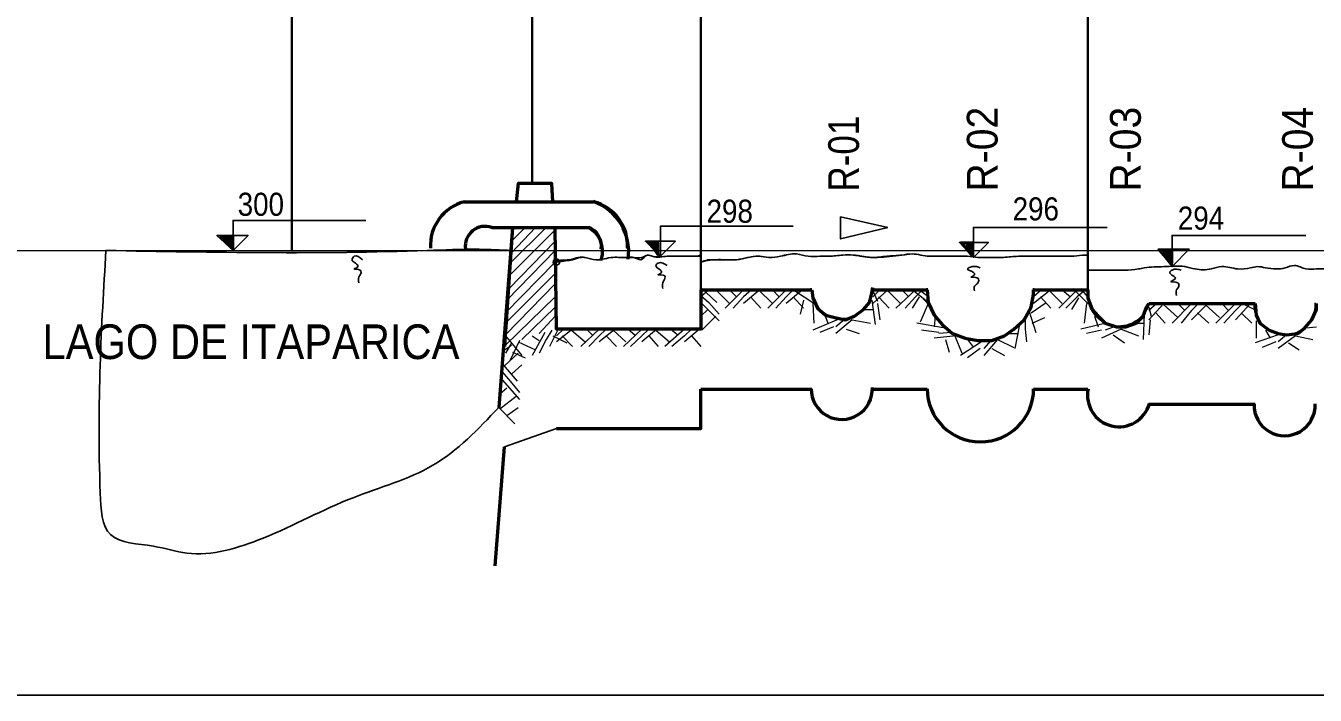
# Model space of a CAD drawing. Extents: x 8426.2 to 8495.4, y 19933.5 to 19963.2.
# Drawn here: x 8432.42 to 8443.58, y 19944.82 to 19950.61 of the extents above; entities that cross this region are included whole.
import ezdxf

# ---------------------------------------------------------------- set-up
doc = ezdxf.new("R2010")
doc.units = 0
doc.header["$LTSCALE"] = 0.11
doc.header["$PDMODE"] = 32
doc.header["$PDSIZE"] = 0.055
for name, color, linetype, lineweight in [('1', 7, 'Continuous', 35), ('2', 7, 'Continuous', 13), ('3', 7, 'Continuous', 25)]:
    doc.layers.add(name, color=color, linetype=linetype, lineweight=lineweight)

msp = doc.modelspace()

# ---------------------------------------------------------------- linework, layer by layer
at = {"layer": '1', "lineweight": 25}
for points in [[(8435.36, 19948.93), (8434.21, 19948.93), (8434.21, 19948.67), (8434.07, 19948.8), (8434.34, 19948.8), (8434.21, 19948.67)], [(8439.06, 19948.88), (8437.91, 19948.88), (8437.91, 19948.62), (8437.78, 19948.75), (8438.04, 19948.75), (8437.91, 19948.62)], [(8441.78, 19948.87), (8440.62, 19948.87), (8440.62, 19948.61), (8440.5, 19948.74), (8440.75, 19948.74), (8440.62, 19948.61)], [(8443.5, 19948.8), (8442.34, 19948.8), (8442.34, 19948.53), (8442.22, 19948.68), (8442.49, 19948.68), (8442.34, 19948.53)]]:
    msp.add_lwpolyline(points, dxfattribs=at)
at = {"layer": '1'}
for points in [[(8434.21, 19948.68), (8434.1, 19948.79), (8434.21, 19948.79)], [(8440.61, 19948.62), (8440.51, 19948.74), (8440.61, 19948.74)]]:
    msp.add_lwpolyline(points, close=True, dxfattribs=at)
for points in [[(8434.21, 19948.68), (8434.11, 19948.79), (8434.19, 19948.79), (8434.19, 19948.7), (8434.13, 19948.77), (8434.18, 19948.77), (8434.19, 19948.73), (8434.16, 19948.76)], [(8434.18, 19948.74), (8434.17, 19948.77), (8434.15, 19948.76), (8434.19, 19948.73)], [(8437.91, 19948.62), (8437.8, 19948.74), (8437.89, 19948.74), (8437.89, 19948.63), (8437.82, 19948.74), (8437.89, 19948.74), (8437.89, 19948.65), (8437.84, 19948.73), (8437.89, 19948.73), (8437.89, 19948.68), (8437.86, 19948.71)], [(8437.89, 19948.69), (8437.88, 19948.71), (8437.85, 19948.71), (8437.89, 19948.68)], [(8440.61, 19948.62), (8440.53, 19948.73), (8440.6, 19948.73), (8440.6, 19948.65), (8440.56, 19948.71), (8440.6, 19948.71), (8440.6, 19948.67), (8440.57, 19948.7)], [(8440.6, 19948.68), (8440.58, 19948.71), (8440.57, 19948.71), (8440.6, 19948.67)], [(8442.34, 19948.54), (8442.23, 19948.67), (8442.34, 19948.67), (8442.34, 19948.56), (8442.26, 19948.65), (8442.33, 19948.65), (8442.33, 19948.57), (8442.27, 19948.64), (8442.33, 19948.64), (8442.33, 19948.59), (8442.31, 19948.63)], [(8442.33, 19948.62), (8442.32, 19948.64), (8442.28, 19948.63), (8442.33, 19948.59)]]:
    msp.add_lwpolyline(points, dxfattribs=at)
at = {"layer": '1', "lineweight": 25}
for points in [[(8435.33, 19948.59), (8435.26, 19948.62), (8435.24, 19948.59), (8435.27, 19948.56), (8435.29, 19948.53), (8435.26, 19948.51), (8435.31, 19948.5), (8435.32, 19948.48), (8435.3, 19948.44), (8435.3, 19948.39)], [(8437.97, 19948.54), (8437.89, 19948.56), (8437.87, 19948.54), (8437.91, 19948.5), (8437.92, 19948.48), (8437.89, 19948.46), (8437.95, 19948.45), (8437.95, 19948.43), (8437.93, 19948.39), (8437.93, 19948.34)], [(8440.68, 19948.52), (8440.61, 19948.53), (8440.57, 19948.51), (8440.62, 19948.48), (8440.63, 19948.46), (8440.6, 19948.44), (8440.66, 19948.43), (8440.66, 19948.39), (8440.63, 19948.36), (8440.63, 19948.32)], [(8440.68, 19948.52), (8440.61, 19948.53), (8440.57, 19948.51), (8440.62, 19948.48), (8440.63, 19948.46), (8440.6, 19948.44), (8440.66, 19948.43), (8440.66, 19948.39), (8440.63, 19948.36), (8440.63, 19948.32)], [(8442.42, 19948.5), (8442.34, 19948.5), (8442.32, 19948.48), (8442.35, 19948.45), (8442.37, 19948.43), (8442.33, 19948.4), (8442.39, 19948.39), (8442.4, 19948.36), (8442.38, 19948.33), (8442.38, 19948.28)]]:
    msp.add_spline(points, degree=3, dxfattribs=at)
at = {"layer": '2', "lineweight": 35}
for p, q in [((8436.8, 19955.32), (8436.8, 19949.25)), ((8438.26, 19955.32), (8438.26, 19948.33)), ((8441.61, 19955.32), (8441.61, 19948.33)), ((8434.72, 19955.24), (8434.72, 19948.67))]:
    msp.add_line(p, q, dxfattribs=at)
at = {"layer": '2', "lineweight": 53}
for p, q in [((8436.21, 19949.09), (8437.33, 19949.09)), ((8436.45, 19948.87), (8437.3, 19948.87)), ((8436.63, 19948.87), (8436.51, 19947.31)), ((8436.63, 19948.87), (8436.56, 19947.84)), ((8438.26, 19948.33), (8439.22, 19948.33)), ((8439.75, 19948.33), (8440.22, 19948.33)), ((8441.14, 19948.33), (8441.61, 19948.33)), ((8442.14, 19948.21), (8443.06, 19948.21)), ((8438.26, 19947.47), (8439.22, 19947.47)), ((8439.75, 19947.47), (8440.22, 19947.47)), ((8441.14, 19947.47), (8441.61, 19947.47)), ((8442.14, 19947.34), (8443.06, 19947.34)), ((8436.48, 19945.94), (8436.56, 19946.97))]:
    msp.add_line(p, q, dxfattribs=at)
at = {"layer": '2', "lineweight": 25}
for p, q in [((8436.6, 19948.45), (8437, 19948.85)), ((8436.61, 19948.56), (8436.92, 19948.87)), ((8436.62, 19948.65), (8436.83, 19948.87)), ((8436.63, 19948.86), (8436.65, 19948.87)), ((8436.63, 19948.76), (8436.74, 19948.87)), ((8436.58, 19948.24), (8437, 19948.67)), ((8436.6, 19948.34), (8437, 19948.75)), ((8436.57, 19948.13), (8437, 19948.57)), ((8436.57, 19948.04), (8437, 19948.47)), ((8436.57, 19947.94), (8437, 19948.38)), ((8436.57, 19947.85), (8437, 19948.27)), ((8436.71, 19947.9), (8437, 19948.18)), ((8436.86, 19947.95), (8437, 19948.1))]:
    msp.add_line(p, q, dxfattribs=at)
at = {"layer": '2'}
for p, q in [((8438.26, 19948.35), (8438.4, 19948.22)), ((8438.33, 19948.33), (8438.26, 19948.27)), ((8438.39, 19948.33), (8438.51, 19948.21)), ((8438.63, 19948.33), (8438.47, 19948.17)), ((8438.51, 19948.33), (8438.57, 19948.27)), ((8438.7, 19948.33), (8438.63, 19948.27)), ((8438.77, 19948.33), (8438.63, 19948.21)), ((8438.76, 19948.33), (8438.88, 19948.21)), ((8439, 19948.33), (8438.84, 19948.17)), ((8438.88, 19948.33), (8438.94, 19948.27)), ((8439.06, 19948.33), (8439, 19948.27)), ((8439.14, 19948.33), (8439, 19948.21)), ((8439.81, 19948.33), (8439.75, 19948.27)), ((8439.88, 19948.33), (8439.75, 19948.21)), ((8439.87, 19948.33), (8439.99, 19948.21)), ((8440.12, 19948.33), (8439.95, 19948.17)), ((8440, 19948.33), (8440.06, 19948.27)), ((8440.24, 19948.21), (8440.09, 19948.33)), ((8440.18, 19948.33), (8440.12, 19948.27)), ((8440.23, 19948.27), (8440.15, 19948.33)), ((8441.21, 19948.33), (8441.14, 19948.27)), ((8441.29, 19948.33), (8441.14, 19948.21)), ((8441.27, 19948.33), (8441.39, 19948.21)), ((8441.52, 19948.33), (8441.36, 19948.17)), ((8441.39, 19948.33), (8441.46, 19948.27)), ((8441.61, 19948.21), (8441.48, 19948.34)), ((8441.61, 19948.21), (8441.48, 19948.34)), ((8441.59, 19948.33), (8441.52, 19948.27)), ((8441.61, 19948.27), (8441.55, 19948.34)), ((8441.61, 19948.27), (8441.55, 19948.34)), ((8438.26, 19948.28), (8438.33, 19948.22)), ((8438.26, 19948.22), (8438.42, 19948.06)), ((8438.33, 19948.22), (8438.42, 19948.12)), ((8438.63, 19948.27), (8438.54, 19948.17)), ((8438.69, 19948.27), (8438.78, 19948.17)), ((8439, 19948.27), (8438.91, 19948.17)), ((8439.06, 19948.27), (8439.15, 19948.17)), ((8439.24, 19948.21), (8439.07, 19948.32)), ((8439.15, 19948.24), (8439.12, 19948.12)), ((8439.74, 19948.24), (8439.77, 19948.03)), ((8439.75, 19948.32), (8439.79, 19948.23)), ((8439.8, 19948.27), (8439.89, 19948.17)), ((8440.12, 19948.27), (8440.03, 19948.17)), ((8440.15, 19948.27), (8440.09, 19948.17)), ((8440.17, 19948.27), (8440.26, 19948.17)), ((8441.12, 19948.13), (8441.25, 19948.22)), ((8441.2, 19948.27), (8441.29, 19948.17)), ((8441.52, 19948.27), (8441.42, 19948.17)), ((8441.53, 19948.26), (8441.47, 19948.16)), ((8441.53, 19948.26), (8441.47, 19948.16)), ((8438.26, 19948.1), (8438.32, 19948.16)), ((8439.23, 19948.21), (8439.24, 19948.04)), ((8439.33, 19948.12), (8439.36, 19948.04)), ((8439.67, 19948.16), (8439.75, 19948.16)), ((8439.79, 19948.21), (8439.81, 19948.07)), ((8440.23, 19948.21), (8440.16, 19948.05)), ((8441.1, 19948.15), (8441.16, 19947.96)), ((8441.6, 19948.21), (8441.58, 19948.04)), ((8441.6, 19948.21), (8441.58, 19948.04)), ((8442.1, 19948.12), (8442.09, 19947.9)), ((8442.21, 19948.21), (8442.14, 19948.15)), ((8442.27, 19948.21), (8442.14, 19948.07)), ((8442.14, 19948.18), (8442.16, 19948.1)), ((8442.2, 19948.13), (8442.28, 19948.04)), ((8442.27, 19948.2), (8442.39, 19948.09)), ((8442.51, 19948.21), (8442.34, 19948.04)), ((8442.39, 19948.21), (8442.45, 19948.15)), ((8442.51, 19948.15), (8442.42, 19948.04)), ((8442.57, 19948.21), (8442.51, 19948.15)), ((8442.65, 19948.21), (8442.51, 19948.07)), ((8442.56, 19948.13), (8442.66, 19948.04)), ((8442.63, 19948.2), (8442.75, 19948.09)), ((8442.89, 19948.21), (8442.72, 19948.04)), ((8442.77, 19948.21), (8442.83, 19948.15)), ((8442.89, 19948.15), (8442.79, 19948.04)), ((8442.95, 19948.21), (8442.89, 19948.15)), ((8443.02, 19948.21), (8442.89, 19948.07)), ((8442.94, 19948.13), (8443.03, 19948.04)), ((8443.07, 19948.15), (8442.97, 19948.2)), ((8438.27, 19947.98), (8438.39, 19948.1)), ((8439.44, 19948.07), (8439.23, 19947.98)), ((8439.41, 19948.01), (8439.29, 19947.96)), ((8439.5, 19948.07), (8439.43, 19948.01)), ((8439.57, 19948.07), (8439.43, 19947.95)), ((8439.57, 19948.07), (8439.73, 19948.04)), ((8440.36, 19948), (8440.13, 19948.04)), ((8440.29, 19948.1), (8440.28, 19948.01)), ((8441.02, 19948.03), (8440.98, 19947.82)), ((8441.07, 19948.09), (8441.07, 19947.99)), ((8441.13, 19948.04), (8441.24, 19948.09)), ((8441.77, 19948.04), (8441.55, 19947.99)), ((8441.77, 19948.04), (8441.55, 19947.99)), ((8441.67, 19948.1), (8441.7, 19948.01)), ((8441.67, 19948.1), (8441.7, 19948.01)), ((8441.84, 19948.01), (8441.76, 19947.98)), ((8441.84, 19948.01), (8441.76, 19947.98)), ((8442.01, 19948.04), (8442.1, 19948.04)), ((8442.15, 19948.07), (8442.14, 19947.94)), ((8443.07, 19948.06), (8443.07, 19947.91)), ((8443.5, 19948), (8443.59, 19948.01)), ((8436.57, 19947.93), (8436.71, 19947.76)), ((8437.07, 19947.99), (8437.01, 19947.93)), ((8437.15, 19947.99), (8437.01, 19947.88)), ((8437.06, 19947.93), (8437.15, 19947.84)), ((8437.14, 19947.98), (8437.26, 19947.88)), ((8437.38, 19947.99), (8437.22, 19947.84)), ((8437.27, 19947.99), (8437.32, 19947.94)), ((8437.38, 19947.93), (8437.29, 19947.84)), ((8437.44, 19947.99), (8437.38, 19947.93)), ((8437.52, 19947.99), (8437.38, 19947.88)), ((8437.44, 19947.93), (8437.53, 19947.84)), ((8437.5, 19947.98), (8437.61, 19947.88)), ((8437.75, 19947.99), (8437.59, 19947.84)), ((8437.63, 19947.99), (8437.69, 19947.94)), ((8437.75, 19947.93), (8437.65, 19947.84)), ((8437.81, 19947.99), (8437.75, 19947.93)), ((8437.88, 19947.99), (8437.75, 19947.88)), ((8437.81, 19947.93), (8437.89, 19947.84)), ((8437.87, 19947.98), (8437.99, 19947.88)), ((8438.12, 19947.99), (8437.95, 19947.84)), ((8438, 19947.99), (8438.06, 19947.94)), ((8438.12, 19947.93), (8438.01, 19947.84)), ((8438.18, 19947.99), (8438.12, 19947.93)), ((8438.25, 19947.99), (8438.12, 19947.88)), ((8438.18, 19947.93), (8438.26, 19947.84)), ((8439.52, 19947.99), (8439.63, 19947.95)), ((8440.32, 19947.96), (8440.17, 19947.98)), ((8440.47, 19947.93), (8440.28, 19947.91)), ((8440.43, 19947.96), (8440.32, 19947.95)), ((8440.38, 19947.9), (8440.41, 19947.79)), ((8440.46, 19947.93), (8440.52, 19947.78)), ((8440.57, 19947.9), (8440.62, 19947.83)), ((8440.83, 19947.9), (8440.71, 19947.76)), ((8440.77, 19947.89), (8440.71, 19947.82)), ((8440.83, 19947.9), (8440.97, 19947.83)), ((8440.92, 19947.95), (8441.01, 19947.95)), ((8441.07, 19947.99), (8441.08, 19947.88)), ((8441.73, 19947.98), (8441.6, 19947.95)), ((8441.73, 19947.98), (8441.6, 19947.95)), ((8441.9, 19947.99), (8441.73, 19947.91)), ((8441.9, 19947.99), (8441.73, 19947.91)), ((8441.83, 19947.94), (8441.93, 19947.87)), ((8441.83, 19947.94), (8441.93, 19947.87)), ((8441.9, 19947.99), (8442.05, 19947.93)), ((8443.26, 19947.94), (8443.06, 19947.87)), ((8443.15, 19947.98), (8443.19, 19947.91)), ((8443.33, 19947.94), (8443.26, 19947.88)), ((8443.41, 19947.93), (8443.26, 19947.82)), ((8443.41, 19947.93), (8443.56, 19947.9)), ((8436.56, 19947.81), (8436.62, 19947.85)), ((8436.56, 19947.67), (8436.68, 19947.78)), ((8440.69, 19947.88), (8440.51, 19947.76)), ((8440.68, 19947.82), (8440.57, 19947.74)), ((8440.78, 19947.82), (8440.89, 19947.76)), ((8443.24, 19947.88), (8443.12, 19947.83)), ((8443.35, 19947.87), (8443.44, 19947.81)), ((8436.55, 19947.68), (8436.67, 19947.54)), ((8436.62, 19947.6), (8436.71, 19947.68)), ((8436.54, 19947.62), (8436.61, 19947.54)), ((8436.54, 19947.55), (8436.69, 19947.38)), ((8436.52, 19947.43), (8436.58, 19947.48)), ((8436.61, 19947.54), (8436.69, 19947.44)), ((8436.52, 19947.3), (8436.66, 19947.41)), ((8436.51, 19947.31), (8436.65, 19947.17)), ((8436.58, 19947.24), (8436.68, 19947.31))]:
    msp.add_line(p, q, dxfattribs=at)
at = {"layer": '2', "lineweight": 53}
for points in [[(8436.98, 19949.09), (8436.97, 19949.25), (8436.68, 19949.25), (8436.66, 19949.09)], [(8438.26, 19948.33), (8438.26, 19947.99), (8437.01, 19947.99), (8437, 19948.87)], [(8437.01, 19947.99), (8437.01, 19947.99), (8437, 19948.87)], [(8439.22, 19948.33), (8439.23, 19948.26), (8439.27, 19948.17), (8439.34, 19948.11), (8439.42, 19948.09), (8439.51, 19948.07), (8439.59, 19948.1), (8439.67, 19948.16), (8439.72, 19948.22), (8439.74, 19948.3), (8439.75, 19948.35)], [(8440.22, 19948.33), (8440.23, 19948.22), (8440.28, 19948.11), (8440.35, 19948.03), (8440.44, 19947.95), (8440.55, 19947.91), (8440.66, 19947.89), (8440.78, 19947.89), (8440.89, 19947.93), (8440.97, 19947.99), (8441.06, 19948.07), (8441.12, 19948.18), (8441.14, 19948.29), (8441.14, 19948.33)], [(8441.61, 19948.33), (8441.61, 19948.26), (8441.65, 19948.16), (8441.7, 19948.1), (8441.76, 19948.04), (8441.86, 19948.01), (8441.94, 19948.01), (8442.03, 19948.04), (8442.09, 19948.1), (8442.12, 19948.18), (8442.14, 19948.21)], [(8443.06, 19948.21), (8443.07, 19948.11), (8443.1, 19948.04), (8443.18, 19947.98), (8443.26, 19947.95), (8443.33, 19947.94), (8443.43, 19947.95), (8443.49, 19948), (8443.55, 19948.07), (8443.59, 19948.16), (8443.59, 19948.21)], [(8437.01, 19947.13), (8438.26, 19947.13), (8438.26, 19947.47)]]:
    msp.add_lwpolyline(points, dxfattribs=at)
at = {"layer": '2', "lineweight": 25}
msp.add_lwpolyline([(8439.88, 19948.87), (8439.47, 19948.96), (8439.47, 19948.77)], close=True, dxfattribs=at)
at = {"layer": '2', "lineweight": 53}
for centre, radius, start, end in [((8436.316, 19948.708), 0.398, 104.9933, 182.695), ((8437.173, 19948.658), 0.463, 352.2317, 69.9334), ((8437.229, 19948.708), 0.398, 357.305, 75.0067), ((8436.392, 19948.708), 0.171, 70.1002, 188.069), ((8437.175, 19948.662), 0.235, 343.5551, 61.7243), ((8437.229, 19948.708), 0.171, 351.931, 70.1002), ((8439.481, 19947.472), 0.265, 180.0421, 2.5541), ((8440.681, 19947.474), 0.461, 180.1681, 359.8318), ((8441.881, 19947.417), 0.273, 168.2886, 344.5583), ((8443.315, 19947.331), 0.265, 178.1436, 2.5541)]:
    msp.add_arc(centre, radius, start, end, dxfattribs=at)
at = {"layer": '3', "lineweight": 13}
for p, q in [((8431.27, 19948.67), (8493.73, 19948.67)), ((8437.03, 19948), (8436.95, 19947.84)), ((8436.69, 19947.89), (8436.61, 19947.72)), ((8436.91, 19947.96), (8436.8, 19947.76)), ((8436.8, 19947.93), (8436.86, 19947.89)), ((8436.92, 19947.9), (8436.86, 19947.78)), ((8436.97, 19947.98), (8436.92, 19947.9)), ((8436.98, 19947.93), (8437.1, 19947.87)), ((8436.62, 19947.87), (8436.57, 19947.78)), ((8436.63, 19947.79), (8436.74, 19947.74)), ((8436.68, 19947.88), (8436.83, 19947.81))]:
    msp.add_line(p, q, dxfattribs=at)
at = {"layer": '3'}
for p, q in [((8436.61, 19948.67), (8436.51, 19947.31)), ((8440.22, 19948.33), (8439.75, 19948.33)), ((8441.61, 19948.33), (8441.14, 19948.33)), ((8442.14, 19948.21), (8443.06, 19948.21)), ((8436.56, 19946.97), (8437.01, 19947.13)), ((8431.27, 19944.82), (8493.73, 19944.82))]:
    msp.add_line(p, q, dxfattribs=at)
for points in [[(8438.26, 19948.33), (8438.26, 19947.99), (8437.01, 19947.99), (8437, 19948.71), (8437.01, 19948.57)], [(8439.22, 19948.33), (8438.26, 19948.33), (8438.26, 19948.59), (8438.26, 19948.57), (8438.29, 19948.58), (8438.3, 19948.58), (8438.32, 19948.59), (8438.33, 19948.59), (8438.34, 19948.59), (8438.35, 19948.59)]]:
    msp.add_lwpolyline(points, dxfattribs=at)
for centre, radius, start, end in [((8439.481, 19948.345), 0.265, 180.0421, 359.9578), ((8440.681, 19948.346), 0.461, 180.1681, 359.8318), ((8441.881, 19948.289), 0.273, 168.2886, 344.5583), ((8443.315, 19948.204), 0.265, 178.1436, 2.5541)]:
    msp.add_arc(centre, radius, start, end, dxfattribs=at)
for points in [[(8436.51, 19947.31), (8435.94, 19946.81), (8435.25, 19946.53), (8434.47, 19946.18), (8433.81, 19946.05), (8433.52, 19946.11), (8433.15, 19946.21), (8433.06, 19946.57), (8433.11, 19948.67)], [(8436.62, 19948.67), (8436.34, 19948.68), (8435.89, 19948.67), (8433.11, 19948.67)], [(8433.11, 19948.67), (8435.89, 19948.67), (8436.33, 19948.68), (8436.61, 19948.67)], [(8437, 19948.57), (8437.02, 19948.58), (8437.13, 19948.59), (8437.2, 19948.61), (8437.26, 19948.61)], [(8437.01, 19948.57), (8437.09, 19948.58), (8437.15, 19948.59), (8437.22, 19948.61), (8437.26, 19948.61)], [(8437.26, 19948.61), (8437.35, 19948.59), (8437.5, 19948.61), (8437.63, 19948.61), (8437.68, 19948.61), (8437.74, 19948.59), (8437.8, 19948.63), (8437.84, 19948.62), (8437.97, 19948.62), (8438.05, 19948.62), (8438.13, 19948.62), (8438.18, 19948.62), (8438.22, 19948.62), (8438.26, 19948.63)], [(8437.26, 19948.61), (8437.35, 19948.59), (8437.41, 19948.59)], [(8437.63, 19948.61), (8437.66, 19948.61), (8437.75, 19948.61), (8437.8, 19948.63), (8437.84, 19948.62), (8437.97, 19948.62), (8438.05, 19948.62), (8438.12, 19948.62), (8438.18, 19948.62), (8438.23, 19948.62), (8438.26, 19948.62)], [(8438.26, 19948.57), (8438.3, 19948.58), (8438.45, 19948.59), (8438.57, 19948.59), (8438.77, 19948.62), (8438.85, 19948.61), (8438.95, 19948.62), (8439.09, 19948.64), (8439.19, 19948.62), (8439.29, 19948.62), (8439.37, 19948.62), (8439.49, 19948.63), (8439.58, 19948.63), (8439.73, 19948.61), (8439.79, 19948.61), (8440, 19948.63), (8440.09, 19948.64), (8440.24, 19948.62), (8440.27, 19948.62), (8440.35, 19948.62), (8440.4, 19948.62), (8440.49, 19948.62), (8440.57, 19948.62), (8440.66, 19948.61), (8440.75, 19948.61), (8440.88, 19948.61), (8441.01, 19948.62), (8441.08, 19948.62), (8441.15, 19948.62), (8441.24, 19948.62), (8441.31, 19948.62), (8441.44, 19948.62), (8441.49, 19948.62), (8441.59, 19948.63), (8441.61, 19948.63)], [(8438.35, 19948.59), (8438.41, 19948.59), (8438.47, 19948.59), (8438.57, 19948.59), (8438.76, 19948.62), (8438.85, 19948.61), (8438.95, 19948.62), (8439.09, 19948.64), (8439.19, 19948.62), (8439.29, 19948.62), (8439.37, 19948.62), (8439.49, 19948.63), (8439.58, 19948.63), (8439.74, 19948.61), (8439.87, 19948.62), (8440, 19948.63), (8440.09, 19948.64), (8440.24, 19948.62), (8440.27, 19948.62), (8440.35, 19948.62), (8440.4, 19948.62), (8440.49, 19948.62), (8440.57, 19948.62), (8440.66, 19948.61), (8440.75, 19948.61), (8440.88, 19948.61), (8441.01, 19948.62), (8441.08, 19948.62), (8441.15, 19948.62), (8441.24, 19948.62), (8441.31, 19948.62), (8441.44, 19948.62), (8441.49, 19948.62), (8441.59, 19948.63), (8441.61, 19948.63)], [(8441.61, 19948.5), (8441.8, 19948.5), (8442.05, 19948.51), (8442.1, 19948.52), (8442.27, 19948.53), (8442.45, 19948.53), (8442.54, 19948.51), (8442.68, 19948.51), (8442.77, 19948.53), (8442.91, 19948.51), (8443.02, 19948.52), (8443.08, 19948.53), (8443.15, 19948.52), (8443.24, 19948.51), (8443.32, 19948.52), (8443.4, 19948.54), (8443.5, 19948.51), (8443.59, 19948.51), (8443.69, 19948.51), (8443.79, 19948.51), (8443.94, 19948.54), (8444.05, 19948.54), (8444.15, 19948.52), (8444.27, 19948.52), (8444.41, 19948.52), (8444.52, 19948.51), (8444.59, 19948.54), (8444.72, 19948.56), (8444.82, 19948.56), (8444.88, 19948.54), (8444.96, 19948.53), (8445, 19948.53)], [(8445, 19948.53), (8444.96, 19948.53), (8444.88, 19948.54), (8444.82, 19948.56), (8444.72, 19948.56), (8444.59, 19948.54), (8444.52, 19948.51), (8444.41, 19948.52), (8444.27, 19948.52), (8444.15, 19948.52), (8444.05, 19948.54), (8443.94, 19948.54), (8443.79, 19948.51), (8443.69, 19948.51), (8443.59, 19948.51), (8443.5, 19948.51), (8443.4, 19948.54), (8443.32, 19948.52), (8443.24, 19948.51), (8443.15, 19948.52), (8443.08, 19948.53), (8443.02, 19948.52), (8442.91, 19948.51), (8442.77, 19948.53), (8442.68, 19948.51), (8442.54, 19948.51), (8442.45, 19948.53), (8442.27, 19948.53), (8442.1, 19948.52), (8442.05, 19948.51), (8441.8, 19948.5), (8441.61, 19948.5)]]:
    msp.add_spline(points, degree=3, dxfattribs=at)
msp.add_point((8437.01, 19948.57), dxfattribs=at)

# ---------------------------------------------------------------- texts
at = {"layer": '1'}
for s, width, p in [('R-02', 0.95, (8440.83, 19949.18)), ('R-03', 0.95, (8442.07, 19949.18)), ('R-04', 0.95, (8443.56, 19949.18)), ('R-01', 0.85, (8439.63, 19949.18))]:
    msp.add_text(s, height=0.2665, rotation=90, dxfattribs=dict(at, width=width)).set_placement(p)
at = {"layer": '2', "width": 0.9}
for s, p in [('300', (8434.25, 19948.97)), ('298', (8438.31, 19948.91)), ('296', (8440.96, 19948.93)), ('294', (8442.39, 19948.85))]:
    msp.add_text(s, height=0.1999, dxfattribs=at).set_placement(p)
at = {"layer": '3', "width": 0.9}
msp.add_text('LAGO DE ITAPARICA', height=0.2999, dxfattribs=at).set_placement((8432.56, 19947.73))

doc.saveas('drawing.dxf')
